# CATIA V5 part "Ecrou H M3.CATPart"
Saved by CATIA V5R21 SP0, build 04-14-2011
Part number: Ecrou H M3
Material "Acier": density 7860 kg/m3, Young's modulus 2e+11 Pa, Poisson ratio 0.266, thermal expansion 1.17e-05 1/K
Bounding box of the stored display mesh (mm): x -2.5 to 2.5, y -2.887 to 2.887, z 0 to 2
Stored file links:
  C:\Users\Olivier\Desktop\redaction CATIA (local)\pompe à moteur de ventilation refait\Ecrou H M3.CATPart
  C:\Program Files\Dassault Systemes\B21\win_b64\startup\materials\French\Catalog.CATMaterial
  C:\Program Files\Dassault Systemes\B21\win_b64\resources\graphic\figures\CATIA_EnvironmentMap_Satin_512x512.jpg
  C:\Users\Olivier\Desktop\redaction CATIA (local)\pompe à moteur de ventilation refait\Pompe_a_moteur_de_ventilation.CATProduct
  C:\Users\Olivier\Desktop\redaction CATIA (local)\pompe à moteur de ventilation refait\Ecrou a collerette M5.CATPart
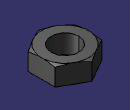
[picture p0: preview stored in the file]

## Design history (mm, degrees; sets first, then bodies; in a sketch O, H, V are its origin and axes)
Body1 (main body), material "Acier"
  Sketch1 on xy-plane, origin (0, 0, 0), H (1, 0, 0), V (0, 1, 0)
    circle A1 centre (0, 0) radius 1.5
    point P1 (2.5, -1.4434)
    point P2 (2.5, 1.4434)
    point P3 (0, 2.8868)
    point P4 (-2.5, 1.4434)
    point P5 (-2.5, -1.4434)
    point P6 (0, -2.8868)
    point P7 (2.5, 0)
    line L1 (2.5, -1.4434) -> (2.5, 1.4434)
    line L2 (2.5, 1.4434) -> (0, 2.8868)
    line L3 (0, 2.8868) -> (-2.5, 1.4434)
    line L4 (-2.5, 1.4434) -> (-2.5, -1.4434)
    line L5 (-2.5, -1.4434) -> (0, -2.8868)
    line L6 (0, -2.8868) -> (2.5, -1.4434)
    construction line L7 (0, 0) -> (2.5, 0)
    construction circle A2 centre (0, 0) radius 2.8868
    construction arc A3 centre (-2.5, -1.4434) radius 2.8868 from (-2.5, 1.4434) to (0, -2.8868) cw
    construction arc A4 centre (2.5, 1.4434) radius 2.8868 from (0, 2.8868) to (2.5, -1.4434) ccw
    distance L1 L4 = 5
    horizontal: L7 H
    coincidence: A2 P1, A2 P2, A2 P3, A2 P4, A2 P5, A2 P6, A3 O, A4 O
    midpoint: P7 L1
  Pad1: profile Sketch1, direction (0, 0, 1), length 2
  Sketch2 on yz-plane, origin (0, 0, 0), H (0, 1, 0), V (0, 0, 1)
    line L1 (2.4595, 2.0276) -> (2.9071, 2.0276)
    point P1 (2.4595, 2.0276)
    line L2 (2.9071, 2.0276) -> (2.9071, 1.8177)
    line L3 (2.9071, 1.8177) -> (2.4663, 2.0244)
    horizontal: L1 H
    vertical: L2 V
    coincidence: L3 P1
  Groove1: profile Sketch2, axis Sketch2.V, angle 360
